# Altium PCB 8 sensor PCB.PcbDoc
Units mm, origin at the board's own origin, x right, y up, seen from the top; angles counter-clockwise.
Board outline 195.58 x 29.21 mm, 2 copper layers (Top Layer, Bottom Layer), stack 1.571 mm thick; 33 components, 18 nets, 80 pads, 0 vias.
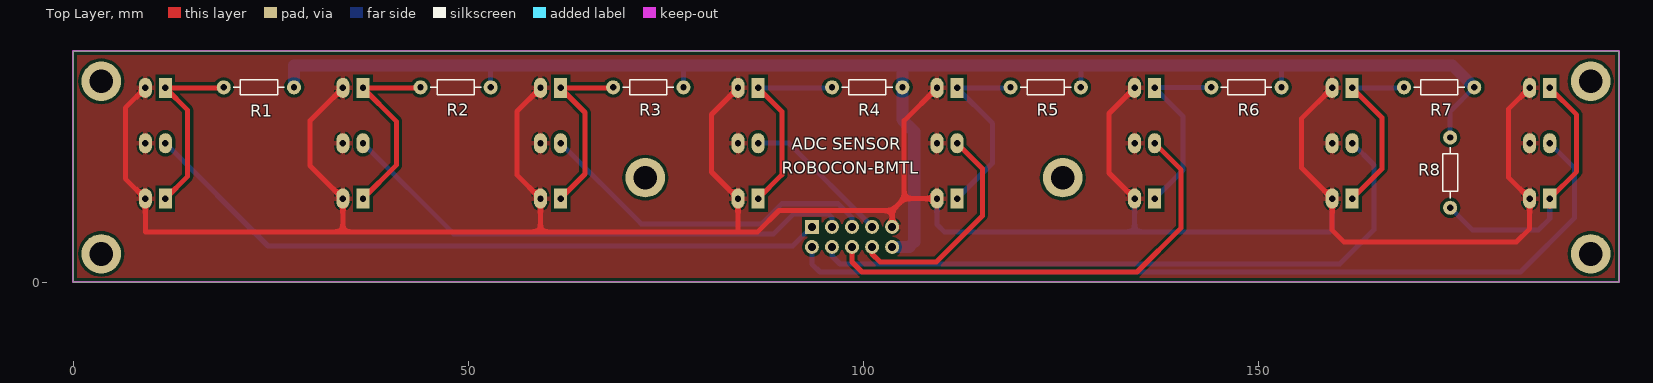
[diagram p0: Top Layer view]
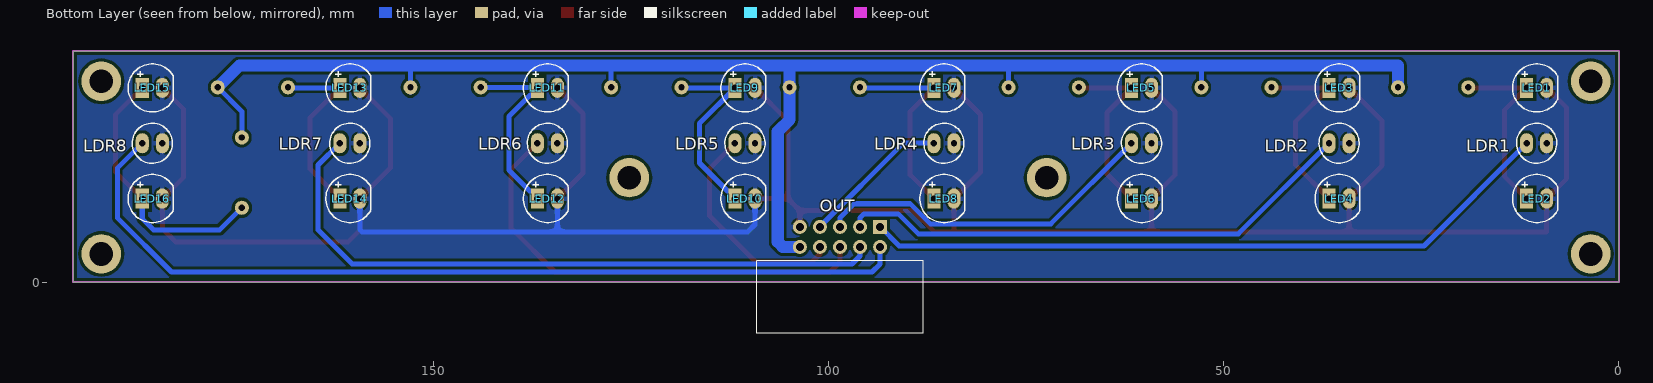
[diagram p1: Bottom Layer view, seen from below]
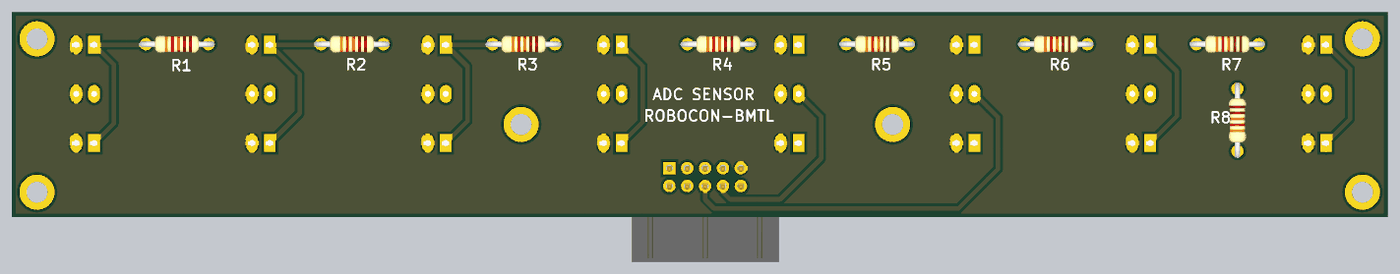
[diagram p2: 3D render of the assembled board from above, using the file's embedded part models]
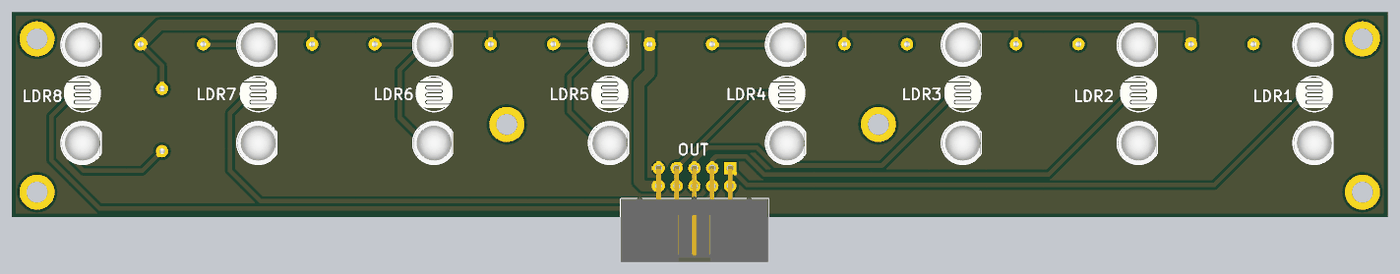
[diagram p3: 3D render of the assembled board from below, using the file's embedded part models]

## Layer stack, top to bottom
Top Solder: solder mask 0.0102, Solder Resist, Dk 3.5
Top Layer: signal copper 0.0356
Dielectric 1: dielectric 1.5, FR-4, Dk 4.8
Bottom Layer: signal copper 0.0356
Bottom Solder: solder mask 0.0102, Solder Resist, Dk 3.5

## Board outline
0,0 0,29.21 195.58,29.21 195.58,0

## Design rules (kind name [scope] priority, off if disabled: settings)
Clearance [All] p1: gap=0.381 ignorepadtopadclearanceinfootprint=FALSE
PolygonConnect [All] p1: connectstyle=Relief reliefconductorwidth=0.635 reliefentries=4 polygonreliefangle="90 Angle" airgapwidth=0.254
RoutingVias [All] p1: holewidth=0.711 width=1.27 viastyle="Through Hole" minholewidth=0.711 minwidth=1.27 maxholewidth=0.711 maxwidth=1.27
SolderMaskExpansion [All] p1: expansion=0.102 istentingtop=FALSE
Width [All] p1: maxlimit=1.524 minlimit=0.254 preferedwidth=0.635
30 further rules are at their usual default settings.

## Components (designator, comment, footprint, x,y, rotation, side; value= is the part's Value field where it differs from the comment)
LDR1 "LDR" CDS 11.668,17.564 r180 bottom
LDR2 "LDR" CDS 36.668,17.564 r180 bottom
LDR3 "LDR" CDS 61.668,17.564 r180 bottom
LDR4 "LDR" CDS 86.668,17.564 r180 bottom
LDR5 "LDR" CDS 111.842,17.564 r180 bottom
LDR6 "LDR" CDS 136.842,17.564 r180 bottom
LDR7 "LDR" CDS 161.842,17.564 r180 bottom
LDR8 "LDR" CDS 186.842,17.564 r180 bottom
LED1 "LED" LED-5-RED 11.668,24.564 r180 bottom value="LED 3 ly Single Colour"
LED2 "LED" LED-5-RED 11.668,10.564 r180 bottom value="LED 3 ly Single Colour"
LED3 "LED" LED-5-RED 36.668,24.564 r180 bottom value="LED 3 ly Single Colour"
LED4 "LED" LED-5-RED 36.668,10.564 r180 bottom value="LED 3 ly Single Colour"
LED5 "LED" LED-5-RED 61.668,24.564 r180 bottom value="LED 3 ly Single Colour"
LED6 "LED" LED-5-RED 61.668,10.564 r180 bottom value="LED 3 ly Single Colour"
LED7 "LED" LED-5-RED 86.668,24.564 r180 bottom value="LED 3 ly Single Colour"
LED8 "LED" LED-5-RED 86.668,10.564 r180 bottom value="LED 3 ly Single Colour"
LED9 "LED" LED-5-RED 111.842,24.564 r180 bottom value="LED 3 ly Single Colour"
LED10 "LED" LED-5-RED 111.842,10.564 r180 bottom value="LED 3 ly Single Colour"
LED11 "LED" LED-5-RED 136.842,24.564 r180 bottom value="LED 3 ly Single Colour"
LED12 "LED" LED-5-RED 136.842,10.564 r180 bottom value="LED 3 ly Single Colour"
LED13 "LED" LED-5-RED 161.842,24.564 r180 bottom value="LED 3 ly Single Colour"
LED14 "LED" LED-5-RED 161.842,10.564 r180 bottom value="LED 3 ly Single Colour"
LED15 "LED" LED-5-RED 186.842,24.564 r180 bottom value="LED 3 ly Single Colour"
LED16 "LED" LED-5-RED 186.842,10.564 r180 bottom value="LED 3 ly Single Colour"
OUT "IDC 5X2" IDC10-BH 98.552,2.032 r0 bottom value="Header 5x2"
R1 "330" R1/4W 19.05,24.638 r0 top value="R1/4W - 1K"
R2 "330" R1/4W 43.942,24.638 r0 top value="R1/4W - 1K"
R3 "330" R1/4W 68.326,24.638 r0 top value="R1/4W - 1K"
R4 "330" R1/4W 96.034,24.638 r0 top value="R1/4W - 1K"
R5 "330" R1/4W 118.618,24.638 r0 top value="R1/4W - 1K"
R6 "330" R1/4W 144.018,24.638 r0 top value="R1/4W - 1K"
R7 "330" R1/4W 168.402,24.638 r0 top value="R1/4W - 1K"
R8 "330" R1/4W 174.244,9.398 r90 top value="R1/4W - 1K"

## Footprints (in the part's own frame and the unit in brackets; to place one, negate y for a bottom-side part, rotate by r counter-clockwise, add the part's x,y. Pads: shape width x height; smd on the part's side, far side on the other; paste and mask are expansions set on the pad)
CDS [mil] "QUANG TRO"
  oval 65x100 hole 32: 1(0,0) 2(100,0)
  silkscreen extent -50,-100 150,100, body extent -53,-80 153,89, height 138
IDC10-BH [mil]
  rect 70x70 hole 40: 1(-200,-195)
  round 70 hole 40: 2(-200,-95) 3(-100,-195) 4(-100,-95) 5(0,-195) 6(0,-95) 7(100,-195) 8(100,-95) 9(200,-195) 10(200,-95)
  silkscreen extent -415,-25 415,335, body extent -412,-204 412,330, height 354
LED-5-RED [mil] "LED 2 PIN, 5 ly , Only colour,pin to pin 100mil"
  rect 65x100 hole 32: 1(0,0)
  oval 65x100 hole 32: 2(100,0)
  silkscreen extent -70,-120 154,120, body extent -65,-119 149,118, height 339
R1/4W [mil] "R 1/4W, 2 Pin, 350mil"
  round 70 hole 31: 1(0,0) 2(350,0)
  silkscreen extent 48,-38 302,38, body extent -40,-47 386,47, height 111

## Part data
LDR1 LDR2 LDR3 LDR4 LDR5 LDR6 LDR7 LDR8: "Quang Tro"
LED1 LED2 LED3 LED4 LED5 LED6 LED7 LED8 LED9 LED10 LED11 LED12 LED13 LED14 LED15 LED16: "LED Single colour Green and Red"
OUT: "Header, 5X2-Pin"
R1 R2 R3 R4 R5 R6 R7 R8: library part R, "Resistor 1/4W"

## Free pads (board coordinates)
  round 5 hole 3: 2(3.556,3.556) 2(3.556,25.4) 2(72.39,13.208) 2(125.222,13.208) 2(192.024,3.556) 2(192.024,25.4)

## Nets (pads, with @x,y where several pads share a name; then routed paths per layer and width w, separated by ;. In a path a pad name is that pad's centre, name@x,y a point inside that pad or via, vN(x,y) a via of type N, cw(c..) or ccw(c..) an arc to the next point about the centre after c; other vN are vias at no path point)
1: LDR1.1 OUT.1 | length 88.2
  Bottom Layer w0.635: LDR1.1 24.66,4.572 91.059,4.572 OUT.1
2: LDR2.1 OUT.3 | length 66.5
  Bottom Layer w0.635: LDR2.1 48.136,6.096 88.646,6.096 91.186,8.636 95.504,8.636 96.012,8.128 OUT.3
3: LDR3.1 OUT.5 | length 44
  Bottom Layer w0.635: LDR3.1 71.866,7.366 87.122,7.366 89.662,9.906 96.774,9.906 98.552,8.128 OUT.5
4: LDR4.1 OUT.7 | length 18.8
  Bottom Layer w0.635: LDR4.1 90.553,17.564 101.092,7.025 OUT.7
5: LDR5.1 OUT.8 | length 28.2
  Top Layer w0.635: OUT.8 101.092,3.556 102.108,2.54 109.22,2.54 115.062,8.382 115.062,14.344 LDR5.1
6: LDR6.1 OUT.6 | length 58.5
  Top Layer w0.635: OUT.6 98.552,2.54 99.822,1.27 134.62,1.27 140.208,6.858 140.208,14.198 LDR6.1
7: LDR7.1 OUT.4 | length 84
  Bottom Layer w0.635: OUT.4 96.012,3.302 97.028,2.286 160.274,2.286 164.592,6.604 164.592,14.814 LDR7.1
8: LDR8.1 OUT.2 | length 112.7
  Bottom Layer w0.635: OUT.2 93.472,2.286 94.488,1.27 183.134,1.27 189.992,8.128 189.992,14.414 LDR8.1
GND: LDR1.2 LDR2.2 LDR3.2 LDR4.2 LDR5.2 LDR6.2 LDR7.2 LDR8.2 LED1.2 LED2.2 LED3.2 LED4.2 LED5.2 LED6.2 LED7.2 LED8.2 LED9.2 LED10.2 LED11.2 LED12.2 LED13.2 LED14.2 LED15.2 LED16.2 OUT.9 | length 351.4
  Top Layer w0.635: LED1.2 6.604,22.04 6.604,13.088 LED2.2 9.128,6.35 34.128,6.35 ; LED3.2 29.972,20.408 29.972,14.72 LED4.2 34.128,6.35 ; LED5.2 56.134,21.57 56.134,13.558 LED6.2 59.128,6.35 ; LED7.2 80.772,21.208 80.772,13.92 LED8.2 84.128,6.404 84.074,6.35 ; OUT.9 103.632,9.04 ; LED10.2 105.156,10.564 ; LED9.2 105.156,20.418 105.156,10.564 ; LED12.2 131.064,13.802 131.064,21.326 LED11.2 ; LED13.2 155.448,20.71 155.448,14.418 LED14.2 159.302,6.56 160.782,5.08 182.626,5.08 184.302,6.756 LED16.2 181.61,13.256 181.61,21.872 LED15.2 ; 34.128,6.35 59.128,6.35 ; 59.128,6.35 84.074,6.35 ; 84.074,6.35 86.614,6.35 89.304,9.04 103.632,9.04 ; 103.632,9.04 105.156,10.564
  Bottom Layer w0.635: LDR2.2 LDR2.2@34.128,18.196 ; LDR3.2 LDR3.2@59.128,18.342 ; LDR4.2 LDR4.2@84.128,17.726 ; LED10.2 109.302,7.284 110.236,6.35 134.302,6.35 ; LED12.2 134.302,6.35 ; LDR6.2 LDR6.2@134.302,17.844 ; LED14.2 159.302,6.648 159.004,6.35 134.302,6.35
NetLED1_1: LED1.1 LED2.1 R1.1 | length 23.7
  Top Layer w0.635: LED2.1 14.478,13.374 14.478,21.754 LED1.1 18.976,24.564 R1.1
NetLED3_1: LED3.1 LED4.1 R2.1 | length 24.8
  Top Layer w0.635: LED4.1 40.894,14.79 40.894,20.338 LED3.1 43.868,24.564 R2.1
NetLED5_1: LED5.1 LED6.1 R3.1 | length 23.3
  Top Layer w0.635: LED6.1 64.77,13.666 64.77,21.462 LED5.1 68.252,24.564 R3.1
NetLED7_1: LED7.1 LED8.1 R4.1 | length 25.8
  Top Layer w0.635: LED8.1 89.662,13.558 89.662,21.57 LED7.1
  Bottom Layer w0.635: LED7.1 R4.1@96.034,24.564
NetLED9_1: LED9.1 LED10.1 R5.1 | length 24.5
  Bottom Layer w0.635: LED10.1 116.332,15.054 116.332,20.074 LED9.1 118.544,24.564 R5.1
NetLED11_1: LED11.1 LED12.1 R6.1 | length 24.2
  Bottom Layer w0.635: LED12.1 140.462,14.184 140.462,20.944 LED11.1 136.916,24.638 R6.1
NetLED13_1: LED13.1 LED14.1 R7.1 | length 23.7
  Top Layer w0.635: LED14.1 165.608,14.33 165.608,20.798 LED13.1
  Bottom Layer w0.635: LED13.1 168.328,24.564 R7.1
NetLED15_1: LED15.1 LED16.1 R8.1 | length 34.7
  Top Layer w0.635: LED16.1@186.842,9.55 LED16.1 190.246,13.968 190.246,21.16 LED15.1
  Bottom Layer w0.635: R8.1 177.038,6.604 185.42,6.604 186.842,8.026 LED16.1
VCC: OUT.10 R1.2 R2.2 R3.2 R4.2 R5.2 R6.2 R7.2 R8.2 | length 199.2
  Bottom Layer w0.635: R1.2@27.94,24.384 R1.2 ; R2.2 52.832,27.378 ; 76.962,27.378 77.216,27.124 R3.2 ; R5.2 127.508,27.378 ; R6.2@152.908,23.958 R6.2 152.908,27.378 ; R8.2 174.244,21.59 R7.2
  Bottom Layer w0.762: 44.55,27.378 44.591,27.337 ; 74.676,27.378 74.757,27.297 ; 104.902,27.378 104.924,27.356 ; 130.265,27.341 130.302,27.378 ; 160.431,27.281 160.528,27.378
  Bottom Layer w1.524: R1.2 27.94,27.378 44.55,27.378 52.832,27.378 74.676,27.378 76.962,27.378 104.902,27.378 127.508,27.378 130.302,27.378 152.908,27.378 160.528,27.378 174.552,27.378 R7.2 ; OUT.10 105.791,4.445 106.426,5.08 106.426,19.05 104.924,20.552 R4.2 104.924,27.356

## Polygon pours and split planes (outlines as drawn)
GND on Bottom Layer "Bottom Layer-GND" (solid, pour order 8): 0,29.21 0,0 195.326,0 195.58,0.254 195.58,29.21
GND on Top Layer "Top Layer-GND" (solid, pour order 10): 0,29.21 0,0.254 0.254,0 195.58,0 195.58,28.956 195.58,29.21

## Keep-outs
Keep-Out Layer:
  the board outline again, w0.254

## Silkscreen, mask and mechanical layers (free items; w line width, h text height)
Top Overlay:
  text "ADC SENSOR" at 90.932,16.764 h1.52
  text "ROBOCON-BMTL" at 89.662,13.716 h1.52

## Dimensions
0,29.21 to 195.58,30.734 on Mechanical 1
